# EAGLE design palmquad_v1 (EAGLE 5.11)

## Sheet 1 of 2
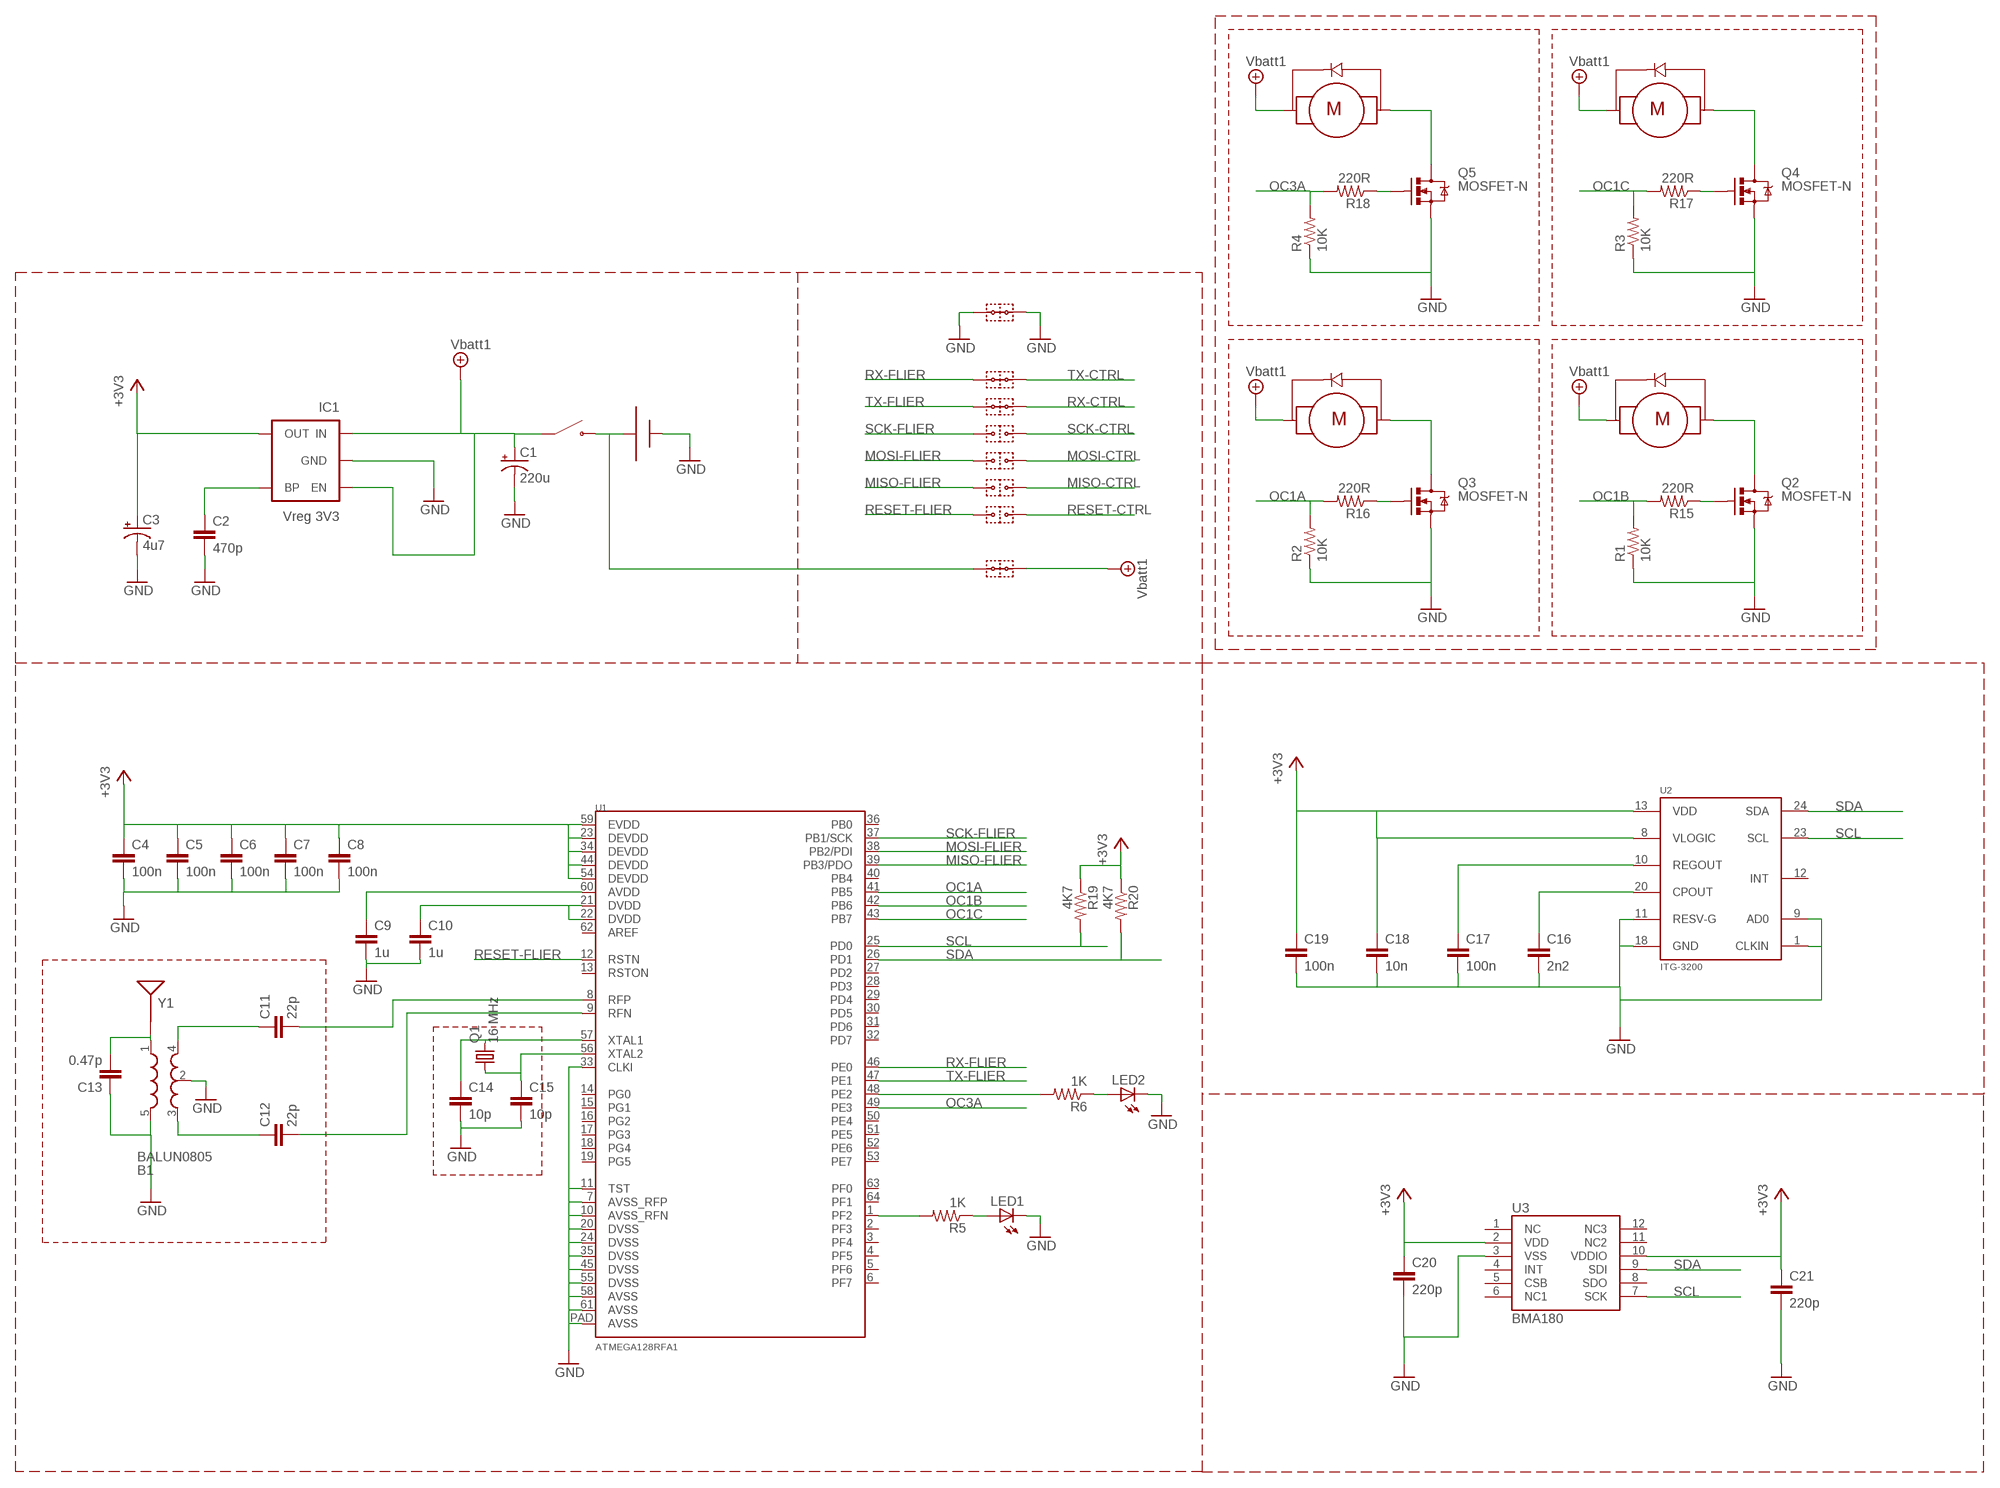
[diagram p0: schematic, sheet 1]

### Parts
B1  BALUN0805  [BALUN]
BATT1  BATT-CONN1  [BATT-CONN-1]
C1  220u  CPOL-USD  [PANASONIC_D]
C2  470p  C-EUC0603  [C0603]
C3  4u7  CPOL-USSMCA  [SMC_A]
C4  100n  C-EUC0603  [C0603]
C5  100n  C-EUC0603  [C0603]
C6  100n  C-EUC0603  [C0603]
C7  100n  C-EUC0603  [C0603]
C8  100n  C-EUC0603  [C0603]
C9  1u  C-EUC0603  [C0603]
C10  1u  C-EUC0603  [C0603]
C11  22p  C-EUC0603  [C0603]
C12  22p  C-EUC0603  [C0603]
C13  0.47p  C-EUC0603  [C0603]
C14  10p  C-EUC0603  [C0603]
C15  10p  C-EUC0603  [C0603]
C16  2n2  C-EUC0603  [C0603]
C17  100n  C-EUC0603  [C0603]
C18  10n  C-EUC0603  [C0603]
C19  100n  C-EUC0603  [C0603]
C20  220p  C-EUC0603  [C0603]
C21  220p  C-EUC0603  [C0603]
IC1  Vreg 3V3  V_REG_LDOSMD  [SOT23-5]
LED1  LEDCHIPLED_0603  [CHIPLED_0603]
LED2  LEDCHIPLED_0603  [CHIPLED_0603]
M1  MOTORARM-CORNER  [MOTOR-CORNER-2]
M2  MOTORARM-CORNER  [MOTOR-CORNER-2]
M3  MOTORARM-CORNER  [MOTOR-CORNER-2]
M4  MOTORARM-CORNER  [MOTOR-CORNER-2]
Q1  16 MHz  CRYSTALCTS406  [CTS406]
Q2  MOSFET-N  MOSFET-NCHANNELSMD  [SOT23-3]
Q3  MOSFET-N  MOSFET-NCHANNELSMD  [SOT23-3]
Q4  MOSFET-N  MOSFET-NCHANNELSMD  [SOT23-3]
Q5  MOSFET-N  MOSFET-NCHANNELSMD  [SOT23-3]
R1  10K  R-US_R0603  [R0603]
R2  10K  R-US_R0603  [R0603]
R3  10K  R-US_R0603  [R0603]
R4  10K  R-US_R0603  [R0603]
R5  1K  R-US_R0603  [R0603]
R6  1K  R-US_R0603  [R0603]
R15  220R  R-US_R0603  [R0603]
R16  220R  R-US_R0603  [R0603]
R17  220R  R-US_R0603  [R0603]
R18  220R  R-US_R0603  [R0603]
R19  4K7  R-US_R0603  [R0603]
R20  4K7  R-US_R0603  [R0603]
S2  SWITCH-PWR-SIMPLE  [SWITCH-PWR]
U1  ATMEGA128RFA1  [QFN-64]
U2  ITG-3200  [QFN-24]
U3  BMA180  [LGA12]
U$1  EDGE-CONN-O-1  [EDGE-CONN-O]
U$2  EDGE-CONN-O-1  [EDGE-CONN-O]
U$3  EDGE-CONN-O-1  [EDGE-CONN-O]
U$4  EDGE-CONN-O-1  [EDGE-CONN-O]
X1  EDGE-CONN-C-1  [EDGE-CONN-C]
X2  EDGE-CONN-C-1  [EDGE-CONN-C]
X5  EDGE-CONN-C-1  [EDGE-CONN-C]
X6  EDGE-CONN-C-1  [EDGE-CONN-C]
Y1  ANTENNA2COMBO1  [ANTENNA-COMBO1]

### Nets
+3V3_FLIER: C3.+ C4.1 C5.1 C6.1 C7.1 C8.1 C18.1 C19.1 C20.1 C21.1 IC1.5(OUT) R19.1 R20.1 U1.23(DEVDD) U1.34(DEVDD) U1.44(DEVDD) U1.54(DEVDD) U1.59(EVDD) U2.8(VLOGIC) U2.13(VDD) U3.2(VDD) U3.10(VDDIO) ; supply symbol labelled +3V3
GND: B1.2(GND) B1.5(GND) BATT1.2 C1.- C2.2 C3.- C4.2 C5.2 C6.2 C7.2 C8.2 C9.2 C10.2 C13.1 C14.2 C15.2 C16.2 C17.2 C18.2 C19.2 C20.2 C21.2 IC1.2(GND) LED1.C LED2.C Q2.2(S) Q3.2(S) Q4.2(S) Q5.2(S) R1.1 R2.1 R3.1 R4.1 U1.7(AVSS_RFP) U1.10(AVSS_RFN) U1.11(TST) U1.20(DVSS) U1.24(DVSS) U1.33(CLKI) U1.35(DVSS) U1.45(DVSS) U1.55(DVSS) U1.58(AVSS) U1.61(AVSS) U1.PAD(AVSS) U2.1(CLKIN) U2.9(AD0) U2.11(RESV-G) U2.18(GND) U3.3(VSS) X6.1 X6.2 ; also sheet 2
MISO-CTRL: U$3.2 ; also sheet 2
MISO-FLIER: U1.39(PB3/PDO) U$3.1
MOSI-CTRL: U$2.2 ; also sheet 2
MOSI-FLIER: U1.38(PB2/PDI) U$2.1
MS1: B1.1(IN) C13.2 Y1.ANT(SIGNAL)
N$1: C2.1 IC1.4(BP)
N$3: C11.2 U1.8(RFP)
N$4: C10.1 U1.21(DVDD) U1.22(DVDD)
N$5: C9.1 U1.60(AVDD)
N$6: B1.3(OUT1) C12.1
N$7: B1.4(OUT2) C11.1
N$8: C12.2 U1.9(RFN)
N$9: C14.1 Q1.3 U1.57(XTAL1)
N$10: C15.1 Q1.1 U1.56(XTAL2)
N$16: C16.1 U2.20(CPOUT)
N$17: C17.1 U2.10(REGOUT)
N$18: M2.B@1 Q3.3(D)
N$19: M3.A@1 Q4.3(D)
N$20: M4.A@1 Q5.3(D)
N$21: M1.B@1 Q2.3(D)
N$23: R5.2 U1.1(PF2)
N$24: LED1.A R5.1
N$40: BATT1.1 S2.P$2 X5.1
N$43: R6.2 U1.48(PE2)
N$44: LED2.A R6.1
N$45: Q5.1(G) R18.1
N$46: Q4.1(G) R17.1
N$47: Q2.1(G) R15.1
N$48: Q3.1(G) R16.1
OC1A: R2.2 R16.2 U1.41(PB5)
OC1B: R1.2 R15.2 U1.42(PB6)
OC1C: R3.2 R17.2 U1.43(PB7)
OC3A: R4.2 R18.2 U1.49(PE3)
RESET-CTRL: U$4.2 ; also sheet 2
RESET-FLIER: U1.12(RSTN) U$4.1
RX-CTRL: X2.2 ; also sheet 2
RX-FLIER: U1.46(PE0) X1.1
SCK-CTRL: U$1.2 ; also sheet 2
SCK-FLIER: U1.37(PB1/SCK) U$1.1
SCL: R19.2 U1.25(PD0) U2.23(SCL) U3.7(SCK)
SDA: R20.2 U1.26(PD1) U2.24(SDA) U3.9(SDI)
TX-CTRL: X1.2 ; also sheet 2
TX-FLIER: U1.47(PE1) X2.1
VBATT-FLIER: C1.+ IC1.1(IN) IC1.3(EN) M1.A@1 M2.A@1 M3.B@1 M4.B@1 S2.P$1 ; supply symbol labelled Vbatt1
VBATT_CHG: X5.2 ; supply symbol labelled Vbatt1 ; also sheet 2
Unconnected: U1.2(PF3) U1.3(PF4) U1.4(PF5) U1.5(PF6) U1.6(PF7) U1.13(RSTON) U1.14(PG0) U1.15(PG1) U1.16(PG2) U1.17(PG3) U1.18(PG4) U1.19(PG5) U1.27(PD2) U1.28(PD3) U1.29(PD4) U1.30(PD5) U1.31(PD6) U1.32(PD7) U1.36(PB0) U1.40(PB4) U1.50(PE4) U1.51(PE5) U1.52(PE6) U1.53(PE7) U1.62(AREF) U1.63(PF0) U1.64(PF1) U2.12(INT) U3.1(NC) U3.4(INT) U3.5(CSB) U3.6(NC1) U3.8(SDO) U3.11(NC2) U3.12(NC3)

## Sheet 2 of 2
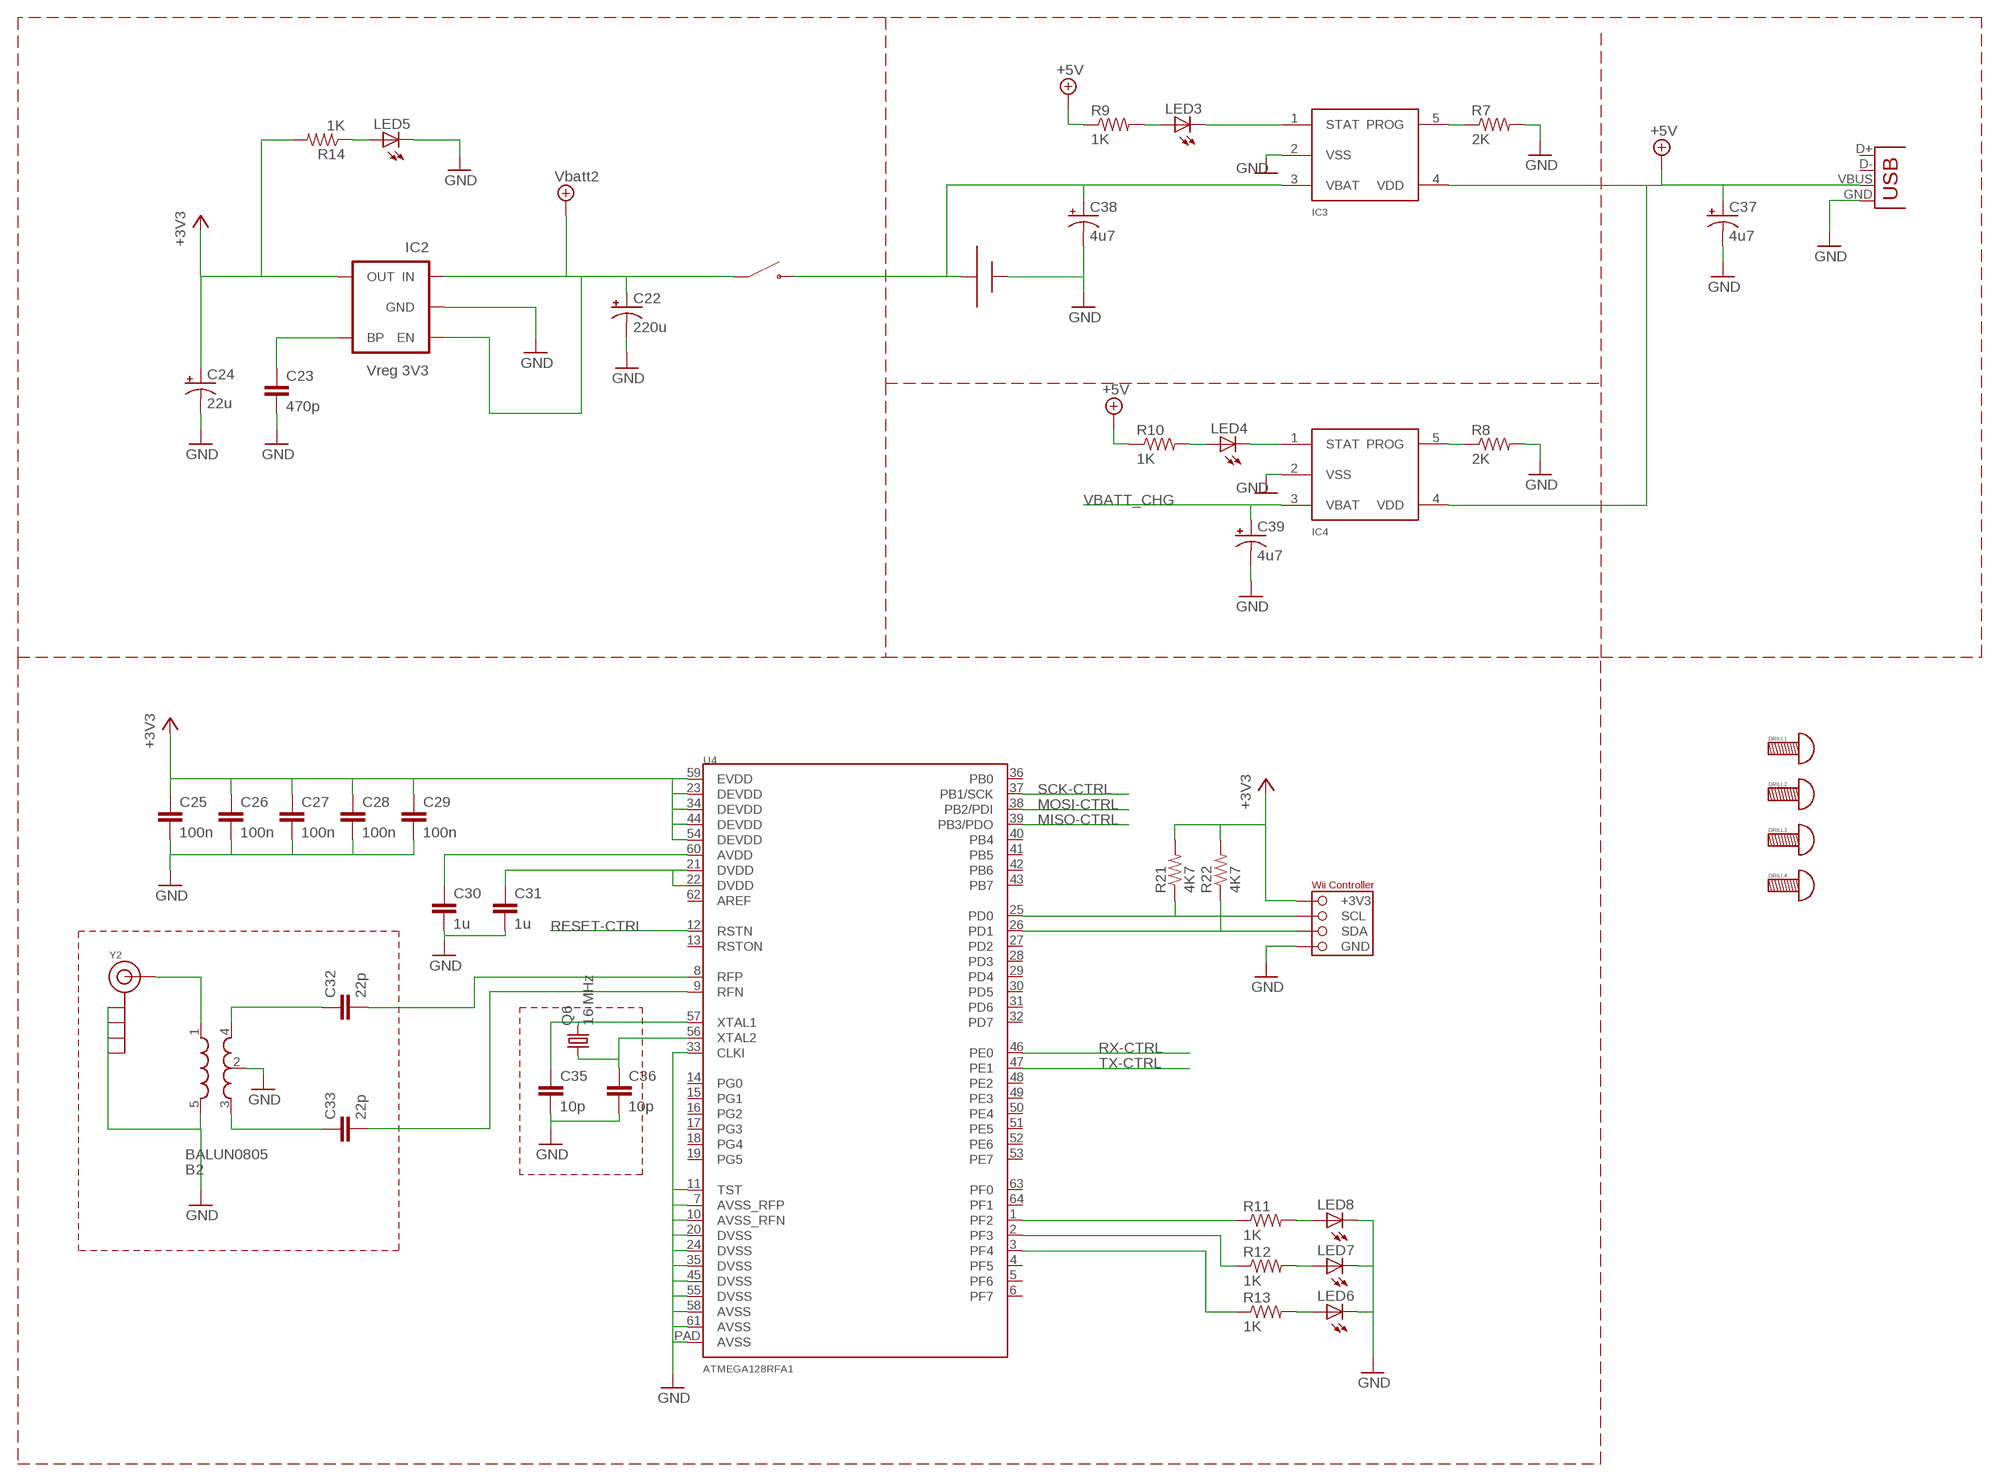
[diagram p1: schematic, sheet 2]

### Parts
B2  BALUN0805  [BALUN]
BATT2  BATT-CONN1  [BATT-CONN-1]
C22  220u  CPOL-USSMCC  [SMC_C]
C23  470p  C-EUC0603  [C0603]
C24  22u  CPOL-USSMCB  [SMC_B]
C25  100n  C-EUC0603  [C0603]
C26  100n  C-EUC0603  [C0603]
C27  100n  C-EUC0603  [C0603]
C28  100n  C-EUC0603  [C0603]
C29  100n  C-EUC0603  [C0603]
C30  1u  C-EUC0603  [C0603]
C31  1u  C-EUC0603  [C0603]
C32  22p  C-EUC0603  [C0603]
C33  22p  C-EUC0603  [C0603]
C35  10p  C-EUC0603  [C0603]
C36  10p  C-EUC0603  [C0603]
C37  4u7  CPOL-USSMCA  [SMC_A]
C38  4u7  CPOL-USSMCA  [SMC_A]
C39  4u7  CPOL-USSMCA  [SMC_A]
DRILL1  HOLE-4-40  [HOLE-4-40]
DRILL2  HOLE-4-40  [HOLE-4-40]
DRILL3  HOLE-4-40  [HOLE-4-40]
DRILL4  HOLE-4-40  [HOLE-4-40]
IC2  Vreg 3V3  V_REG_LDOSMD  [SOT23-5]
IC3  MCP-LI-CHARGER-1  [SOT23-5]
IC4  MCP-LI-CHARGER-1  [SOT23-5]
LED3  LEDCHIPLED_0603  [CHIPLED_0603]
LED4  LEDCHIPLED_0603  [CHIPLED_0603]
LED5  LEDCHIPLED_0603  [CHIPLED_0603]
LED6  LEDCHIPLED_0603  [CHIPLED_0603]
LED7  LEDCHIPLED_0603  [CHIPLED_0603]
LED8  LEDCHIPLED_0603  [CHIPLED_0603]
Q6  16 MHz  CRYSTALCTS406  [CTS406]
R7  2K  R-US_R0603  [R0603]
R8  2K  R-US_R0603  [R0603]
R9  1K  R-US_R0603  [R0603]
R10  1K  R-US_R0603  [R0603]
R11  1K  R-US_R0603  [R0603]
R12  1K  R-US_R0603  [R0603]
R13  1K  R-US_R0603  [R0603]
R14  1K  R-US_R0603  [R0603]
R21  4K7  R-US_R0603  [R0603]
R22  4K7  R-US_R0603  [R0603]
S1  SWITCH-PWR-CNKOS2  [SWITCH-SPDT-CNK-OS2]
U4  ATMEGA128RFA1  [QFN-64]
USB  USBSMD  [USB-MINIB]
X11  WII-CONN  [WII-CONN-2]
Y2  SMA_EDGE  [SMA-EDGE]

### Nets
+3V3_CTRL: C24.+ C25.1 C26.1 C27.1 C28.1 C29.1 IC2.5(OUT) R14.2 R21.2 R22.2 U4.23(DEVDD) U4.34(DEVDD) U4.44(DEVDD) U4.54(DEVDD) U4.59(EVDD) X11.+3V3 ; supply symbol labelled +3V3
GND: B2.2(GND) B2.5(GND) BATT2.2 C22.- C23.2 C24.- C25.2 C26.2 C27.2 C28.2 C29.2 C30.2 C31.2 C35.2 C36.2 C37.- C38.- C39.- IC2.2(GND) IC3.2(VSS) IC4.2(VSS) LED5.C LED6.C LED7.C LED8.C R7.2 R8.2 U4.7(AVSS_RFP) U4.10(AVSS_RFN) U4.11(TST) U4.20(DVSS) U4.24(DVSS) U4.33(CLKI) U4.35(DVSS) U4.45(DVSS) U4.55(DVSS) U4.58(AVSS) U4.61(AVSS) U4.PAD(AVSS) USB.GND X11.GND Y2.GND@0(GND) Y2.GND@1(GND) Y2.GND@2(GND) Y2.GND@3(GND) ; also sheet 1
MISO-CTRL: U4.39(PB3/PDO) ; also sheet 1
MOSI-CTRL: U4.38(PB2/PDI) ; also sheet 1
N$2: LED5.A R14.1
N$11: IC3.5(PROG) R7.1
N$12: LED6.A R13.2
N$13: LED7.A R12.2
N$14: LED8.A R11.2
N$15: IC4.5(PROG) R8.1
N$22: R11.1 U4.1(PF2)
N$25: C23.1 IC2.4(BP)
N$26: C31.1 U4.21(DVDD) U4.22(DVDD)
N$27: C30.1 U4.60(AVDD)
N$28: B2.1(IN) Y2.SIG(SIGNAL)
N$29: B2.3(OUT1) C33.1
N$30: B2.4(OUT2) C32.1
N$31: C32.2 U4.8(RFP)
N$32: C33.2 U4.9(RFN)
N$33: C35.1 Q6.3 U4.57(XTAL1)
N$34: C36.1 Q6.1 U4.56(XTAL2)
N$35: LED3.A R9.2
N$36: IC3.1(STAT) LED3.C
N$37: LED4.A R10.2
N$38: IC4.1(STAT) LED4.C
N$39: BATT2.1 C38.+ IC3.3(VBAT) S1.2
N$41: R12.1 U4.2(PF3)
N$42: R13.1 U4.3(PF4)
RESET-CTRL: U4.12(RSTN) ; also sheet 1
RX-CTRL: U4.46(PE0) ; also sheet 1
SCK-CTRL: U4.37(PB1/SCK) ; also sheet 1
SCL-2: R21.1 U4.25(PD0) X11.SCL
SDA-2: R22.1 U4.26(PD1) X11.SDA
TX-CTRL: U4.47(PE1) ; also sheet 1
VBATT-CTRL: C22.+ IC2.1(IN) IC2.3(EN) S1.1 ; supply symbol labelled Vbatt2
VBATT_CHG: C39.+ IC4.3(VBAT) ; also sheet 1
VUSB: C37.+ IC3.4(VDD) IC4.4(VDD) R9.1 R10.1 USB.VBUS ; supply symbol labelled +5V
Unconnected: U4.4(PF5) U4.5(PF6) U4.6(PF7) U4.13(RSTON) U4.14(PG0) U4.15(PG1) U4.16(PG2) U4.17(PG3) U4.18(PG4) U4.19(PG5) U4.27(PD2) U4.28(PD3) U4.29(PD4) U4.30(PD5) U4.31(PD6) U4.32(PD7) U4.36(PB0) U4.40(PB4) U4.41(PB5) U4.42(PB6) U4.43(PB7) U4.48(PE2) U4.49(PE3) U4.50(PE4) U4.51(PE5) U4.52(PE6) U4.53(PE7) U4.62(AREF) U4.63(PF0) U4.64(PF1) USB.D+ USB.D-

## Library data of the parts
B1 B2 = palmquad_alpha:BALUN
BATT1 BATT2 = palmquad_alpha:BATT-CONN
C1 C3 C22 C24 C37-C39 = rcl:CPOL-US: POLARIZED CAPACITOR, American symbol
C2 C4-C21 C23 C25-C33 C35 C36 = rcl:C-EU: CAPACITOR, European symbol
DRILL1-DRILL4 = palmquad_alpha:HOLE
IC1 IC2 = palmquad_alpha:V_REG_LDO: Voltage Regulator LDO Standard 150mA LDO voltage regulator in SOT-23 layout. Micrel part MIC5205. BP (by-pass) pin is used to lower output noise with 470pF cap.
IC3 IC4 = palmquad_alpha:MCP-LI-CHARGER-1
LED1-LED8 = led:LED: LED
M1-M4 = palmquad_alpha:MOTOR
Q1 Q6 = crystal:CRYSTAL: CRYSTAL
Q2-Q5 = palmquad_alpha:MOSFET-NCHANNEL
R1-R22 = rcl:R-US_: RESISTOR, American symbol
S1 S2 = palmquad_alpha:SWITCH-PWR
U1 U4 = palmquad_alpha:ATMEGA128RFA1
U2 = palmquad_alpha:ITG-3200: ITG-3200 3-axis gyro, digital output, qfn24 package
U3 = palmquad_alpha:BMA180
U$1-U$4 = palmquad_alpha:EDGE-CONN-O
USB = palmquad_alpha:USB: USB Connectors USB-B-PTH is fully proven SKU : PRT-00139 USB-miniB is fully proven SKU : PRT-00587 USB-A-PCB is untested. USB-A-H is throughly reviewed, but untested. Spark Fun Electronics SKU : PRT-00437 USB-B-SMT is throughly reviewed, but untested. Needs silkscreen touching up. USB-A-S has not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
X1 X2 X5 X6 = palmquad_alpha:EDGE-CONN-C
X11 = palmquad_alpha:WII-CONN
Y1 = palmquad_alpha:ANTENNA2: Antenna
Y2 = palmquad_alpha:SMA_EDGE: SMA Antenna Connector End launch SMA connector. The paste layer has been removed so that the connector can be hand soldered onto the board after reflow.

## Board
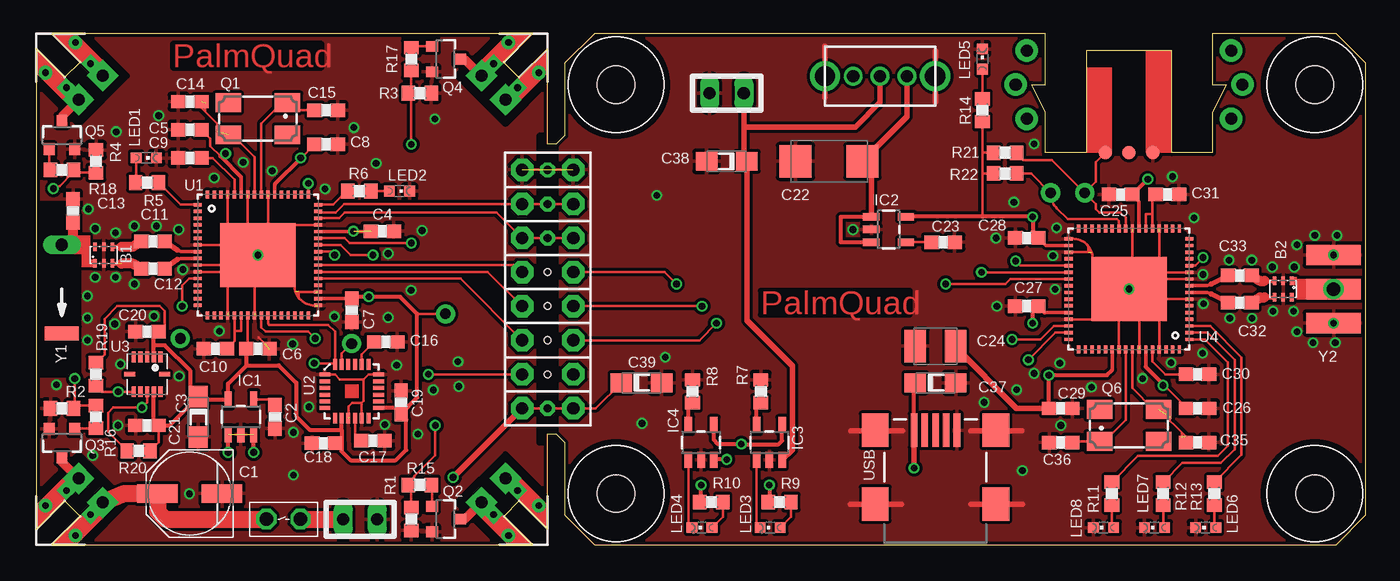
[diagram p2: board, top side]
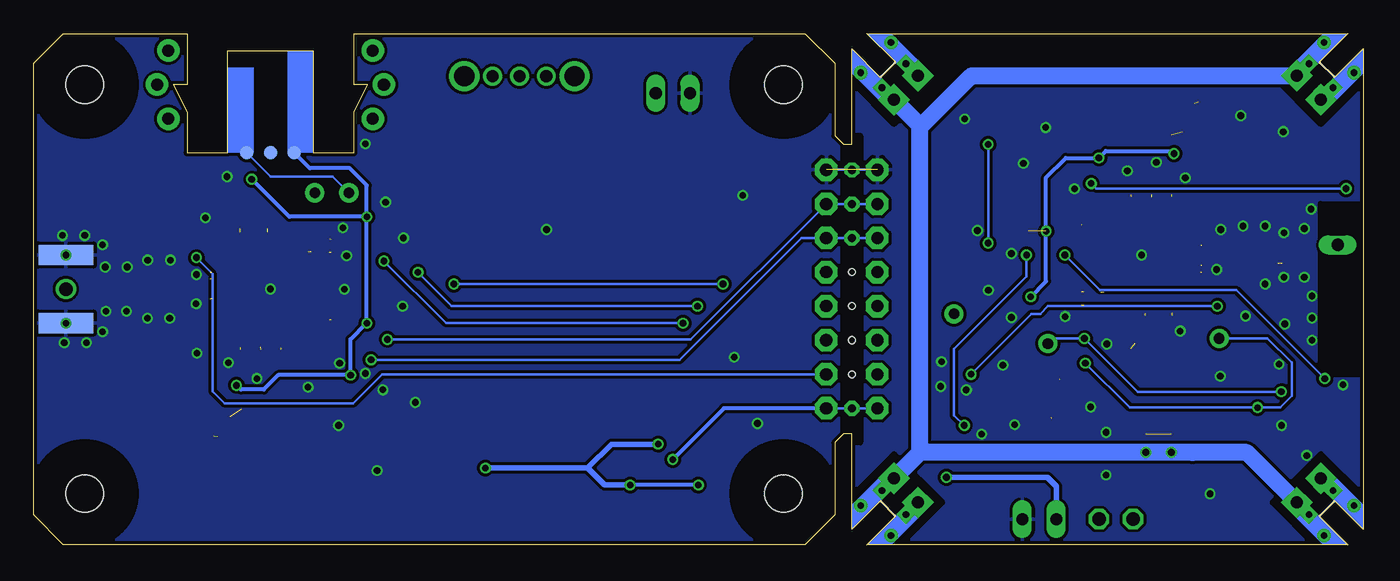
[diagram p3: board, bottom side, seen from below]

Size 99.06 x 38.1 mm. Coordinates in mm from the lower left corner, seen from the top.
Outline: 0,1.14 2.13,3.27 3.27,2.13 1.14,0 36.96,0 34.83,2.13 35.97,3.27 38.1,1.14 38.1,8.26 38.73,8.26 39.37,7.62 39.37,2.22 41.59,0 96.84,0 99.06,2.22 99.06,35.88 96.84,38.1 87.63,38.1 87.63,34.29 88.65,34.29 87.63,32.26 87.63,29.21 84.58,29.21 84.58,36.83 78.23,36.83 78.23,29.21 75.18,29.21 75.18,32.26 74.17,34.29 75.18,34.29 75.18,38.1 41.59,38.1 39.37,35.88 39.37,30.48 38.73,29.84 38.1,29.84 38.1,36.96 36.01,34.86 35.94,34.86 34.86,35.94 34.86,36.01 36.96,38.1 1.14,38.1 3.27,35.97 2.13,34.83 0,36.96 0,1.14
Copper layers (1*16): Top 0.035mm / dielectric 1.5mm / Bottom 0.035mm
Design rules "Fusion_eagle_rule_v1.1_TentedVias3": minimum track width 6mil, minimum drill 0.3mm, track to track 7mil, track to pad 7mil, pad to pad 7mil, via to via 7mil, smd to smd 0mil, copper to edge 10mil, drill to drill 10mil, minimum pad ring 10mil, minimum via ring 6mil, stop-mask expansion 2mil, vias tented up to drill 25mil, thermal gap 10mil
tRestrict: area 0,12.7 to 3.2,25.4; area 37.5,7.6 to 38.7,30.5; area 12.4,17.4 to 20.6,25.7; area 77.3,14.9 to 85.5,23.2; area 7,12 to 9.5,13.4; area 22,10 to 25,12.9; 4 lines
bRestrict: area 0,12.7 to 3.2,25.4; area 37.5,7.6 to 38.7,30.5

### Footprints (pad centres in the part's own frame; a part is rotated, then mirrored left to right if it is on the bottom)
BALUN = smd 0.27 x 0.635: 1 -0.7,-0.616; 2 -0.05,-0.616; 3 0.6,-0.616; 4 0.6,0.616; 5 -0.05,0.616; 6 -0.7,0.616
BATT-CONN-1 = drill 0.9 long: 1 -1.27,0; 2 1.27,0
PANASONIC_D = smd 3 x 1.4: + 2.4,0; - -2.4,0
C0603 = smd 1.1 x 1: 1 -0.85,0; 2 0.85,0
SMC_A = smd 1.6 x 1.4: + -1.5,0; - 1.5,0
SMC_C = smd 2.4 x 2.4: + -2.5,0; - 2.5,0
SMC_B = smd 1.6 x 2.4: + -1.5,0; - 1.5,0
HOLE-4-40 = hole 2.794: 0,0
SOT23-5 = smd 0.55 x 1.2: 1 -0.95,-1.3; 2 0,-1.3; 3 0.95,-1.3; 4 0.95,1.3; 5 -0.95,1.3
CHIPLED_0603 = smd 0.8 x 0.8: A 0,-0.75; C 0,0.75
MOTOR-CORNER-2 = drill 0.9 pad 1.676 square: A@1 -1.27,-5.715; B@1 1.27,-5.715 | drill 0.5 square: A@2 -1.27,-4.445; B@2 1.27,-4.445 | drill 0.5 round: P$1 -1.587,-2.54; P$2 1.587,-2.54
CTS406 = smd 1.9 x 1.4: 1 -2.2,-1.2; 2 2.2,-1.2; 3 2.2,1.2; 4 -2.2,1.2
SOT23-3 = smd 0.8 x 0.9: 1 -0.95,-1; 2 0.95,-1; 3 0,1.1
R0603 = smd 1 x 1.1: 1 -0.85,0; 2 0.85,0
SWITCH-SPDT-CNK-OS2 = drill 0.9 round: 1 0,2.007; 2 0,0; 3 0,-2.007 | drill 1.499 pad 1.905 round: P$4 0,4.102; P$5 0,-4.102
SWITCH-PWR = drill 1 octagon: P$1 -1.27,0; P$2 1.27,0
QFN-64 = smd 0.6 x 0.25: 1 -4.5,3.75; 2 -4.5,3.25; 3 -4.5,2.75; 4 -4.5,2.25; 5 -4.5,1.75; 6 -4.5,1.25; 7 -4.5,0.75; 8 -4.5,0.25; 9 -4.5,-0.25; 10 -4.5,-0.75; 11 -4.5,-1.25; 12 -4.5,-1.75; 13 -4.5,-2.25; 14 -4.5,-2.75; 15 -4.5,-3.25; 16 -4.5,-3.75; 33 4.5,-3.75; 34 4.5,-3.25; 35 4.5,-2.75; 36 4.5,-2.25; 37 4.5,-1.75; 38 4.5,-1.25; 39 4.5,-0.75; 40 4.5,-0.25; 41 4.5,0.25; 42 4.5,0.75; 43 4.5,1.25; 44 4.5,1.75; 45 4.5,2.25; 46 4.5,2.75; 47 4.5,3.25; 48 4.5,3.75 | smd 0.25 x 0.6: 17 -3.75,-4.5; 18 -3.25,-4.5; 19 -2.75,-4.5; 20 -2.25,-4.5; 21 -1.75,-4.5; 22 -1.25,-4.5; 23 -0.75,-4.5; 24 -0.25,-4.5; 25 0.25,-4.5; 26 0.75,-4.5; 27 1.25,-4.5; 28 1.75,-4.5; 29 2.25,-4.5; 30 2.75,-4.5; 31 3.25,-4.5; 32 3.75,-4.5; 49 3.75,4.5; 50 3.25,4.5; 51 2.75,4.5; 52 2.25,4.5; 53 1.75,4.5; 54 1.25,4.5; 55 0.75,4.5; 56 0.25,4.5; 57 -0.25,4.5; 58 -0.75,4.5; 59 -1.25,4.5; 60 -1.75,4.5; 61 -2.25,4.5; 62 -2.75,4.5; 63 -3.25,4.5; 64 -3.75,4.5 | smd 5.639 x 4.75: PAD 0,0
QFN-24 = smd 0.8 x 0.3: 1 -2,1.25; 2 -2,0.75; 3 -2,0.25; 4 -2,-0.25; 5 -2,-0.75; 6 -2,-1.25; 13 2,-1.25; 14 2,-0.75; 15 2,-0.25; 16 2,0.25; 17 2,0.75; 18 2,1.25 | smd 0.3 x 0.8: 7 -1.25,-2; 8 -0.75,-2; 9 -0.25,-2; 10 0.25,-2; 11 0.75,-2; 12 1.25,-2; 19 1.25,2; 20 0.75,2; 21 0.25,2; 22 -0.25,2; 23 -0.75,2; 24 -1.25,2
LGA12 = smd 0.8 x 0.32: 1 -1.3,1; 2 -1.3,0.5; 3 -1.3,0; 4 -1.3,-0.5; 5 -1.3,-1; 7 1.3,-1; 8 1.3,-0.5; 9 1.3,0; 10 1.3,0.5; 11 1.3,1 | smd 0.32 x 0.8: 6 0,-1.3; 12 0,1.3
EDGE-CONN-O = drill 0.9 pad 1.676 octagon: 1 -1.905,0; 2 1.905,0 | hole 0.5: 0,0
USB-MINIB = smd 2.5 x 0.5: D+ 2.5,0; D- 2.5,0.8; GND 2.5,-1.6; ID 2.5,-0.8; VBUS 2.5,1.6 | smd 2.5 x 2: GND@1 -3,-4.5; GND@2 -3,4.5; GND@3 2.5,4.5; GND@4 2.5,-4.5
EDGE-CONN-C = drill 0.9 pad 1.676 octagon: 1 -1.905,0; 2 1.905,0 | drill 0.6 octagon: C 0,0
WII-CONN-2 = smd 1.016 x 1.016 bottom: +3V3 1.778,7.62; DEV_DET 0,7.62; SDA -1.778,7.62 | smd 1.016 x 1.016: GND -1.778,7.62; NC 0,7.62; SCL 1.778,7.62 | drill 0.9 pad 1.676 round: P$4 -7.62,0; P$5 7.62,0; P$6 -7.62,5.08; P$7 7.62,5.08; P$11 -8.445,2.54; P$12 8.445,2.54
ANTENNA-COMBO1 = drill 0.9 long: ANT 3.302,0 | smd 1.016 x 2.54: NC -3.302,0
SMA-EDGE = smd 1.524 x 4.064: GND@0 0,0; GND@1 5.08,0; SIG 2.54,0 | smd 1.524 x 4.064 bottom: GND@2 0,0; GND@3 5.08,0

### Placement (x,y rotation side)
B1  5.08,21.59 0 top
B2  92.84,19.05 180 top
BATT1  24.13,1.91 0 top
BATT2  51.44,33.66 180 top
C1  11.43,3.81 180 top
C2  17.78,9.53 270 top
C3  12.06,9.53 270 top
C4  25.78,23.37 0 top
C5  11.43,30.92 180 top
C6  16.51,14.61 0 top
C7  23.5,17.46 270 top
C8  21.59,29.84 0 top
C9  11.43,28.83 180 top
C10  13.34,14.61 180 top
C11  8.7,22.61 0 top
C12  8.7,20.57 0 top
C13  2.73,24.89 270 top
C14  11.43,33.02 180 top
C15  21.59,32.38 0 top
C16  26.04,15.11 0 top
C17  25.08,7.75 0 top
C18  21.4,7.56 180 top
C19  27.18,10.6 90 top
C20  8.26,15.88 180 top
C21  8.26,8.89 180 top
C22  59.05,28.57 180 top
C23  67.56,22.55 0 top
C24  66.99,14.8 180 top
C25  80.77,26.1 180 top
C26  86.51,10.16 0 top
C27  73.79,17.78 180 top
C28  73.79,22.86 180 top
C29  76.33,10.16 0 top
C30  86.51,12.7 0 top
C31  84.26,26.1 0 top
C32  89.66,18.03 180 top
C33  89.66,20.07 180 top
C35  86.51,7.62 0 top
C36  76.33,7.62 180 top
C37  66.99,12.06 0 top
C38  51.44,28.57 180 top
C39  45.09,12.06 0 top
DRILL1  43.18,3.81 0 top
DRILL2  95.25,3.81 0 top
DRILL3  43.18,34.29 0 top
DRILL4  95.25,34.29 0 top
IC1  15.24,9.53 0 top
IC2  63.5,23.5 270 top
IC3  54.61,7.62 0 top
IC4  49.53,7.62 0 top
LED1  8.19,28.83 270 top
LED2  27.05,26.35 270 top
LED3  54.67,1.27 90 top
LED4  49.59,1.27 90 top
LED5  70.48,36.2 0 top
LED6  87.12,1.27 90 top
LED7  83.31,1.27 90 top
LED8  79.5,1.27 90 top
M1  38.1,0 225 top
M2  0,0 135 top
M3  38.1,38.1 315 top
M4  0,38.1 45 top
Q1  16.51,31.75 180 top
Q2  30.48,1.91 270 top
Q3  1.91,7.62 180 top
Q4  30.48,36.2 270 top
Q5  1.91,30.48 0 top
Q6  81.41,8.89 0 top
R1  27.94,1.91 90 top
R2  1.91,10.16 0 top
R3  28.57,33.66 180 top
R4  4.45,28.57 270 top
R5  8.26,26.99 0 top
R6  24.07,26.35 180 top
R7  53.98,11.43 90 top
R8  48.9,11.43 90 top
R9  55.37,3.17 0 top
R10  50.29,3.17 0 top
R11  80.14,3.81 270 top
R12  83.95,3.81 270 top
R13  87.76,3.81 270 top
R14  70.48,32.38 270 top
R15  28.57,4.45 180 top
R16  4.45,9.53 90 top
R17  27.94,36.2 270 top
R18  1.91,27.94 0 top
R19  4.45,12.7 270 top
R20  7.62,6.99 180 top
R21  72.17,29.21 180 top
R22  72.17,27.67 180 top
S1  62.87,34.92 270 top
S2  18.41,1.91 0 top
U1  16.51,21.59 0 top
U2  23.5,11.43 0 top
U3  8.26,12.7 270 top
U4  81.41,19.05 180 top
U$1  38.1,15.24 0 top
U$2  38.1,17.78 0 top
U$3  38.1,20.32 0 top
U$4  38.1,12.7 0 top
U$5  [ARM-MOCK]  35.56,35.56 45 top
U$6  [ARM-MOCK]  2.54,35.56 135 top
U$7  [ARM-MOCK]  2.54,2.54 225 top
U$8  [ARM-MOCK]  35.56,2.54 315 top
USB  66.99,6.03 90 top
X1  38.1,22.86 0 top
X2  38.1,25.4 0 top
X5  38.1,10.16 0 top
X6  38.1,27.94 180 top
X11  81.41,36.83 180 top
Y1  1.91,19.05 90 top
Y2  96.65,16.51 90 top

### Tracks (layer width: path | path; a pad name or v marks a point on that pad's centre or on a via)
+3V3_CTRL  (via drill 0.5)
  Top 0.203: C29.1 75.45,10.19 | C29.1 75.48,10.23 | C26.1 85.64,10.27 83.89,12.01 83.69,12.01 | C25.1 81.62,25.82 | C29.1 75.44,10.16 | 74.23,17.38 C27.1 | 70.48,24.45 70.48,27.67 | 70.48,29.21 R14.2 | 70.48,29.21 R21.2 | 70.48,27.67 R22.2 | 70.48,27.67 70.48,29.21
  Top 0.254: U4.34 75.2,22.3 C28.1 | 75.12,17.3 U4.44 | 80.16,13.03 U4.54 | 82.66,13.25 U4.59 | U4.23 82.16,25.56 C25.1
  Top 0.305: C27.1 75.12,17.3 | 82.66,13.25 83.89,12.01 83.95,11.96 v83.95,11.87 | 80.16,13.03 79.76,12.64 v75.44,12.64 75.44,10.16 | v74.23,16.51 74.23,17.38 | v82.8,27.24 81.66,26.1 C25.1 | C28.1 74.23,23.27 v74.23,24.45 70.48,24.45 IC2.5
  Top 0.406: C24.+ 68.39,14.8 73.03,10.16 C29.1
  Bottom 0.305: X11.+3V3 78.49,28.07 75.5,28.07 74.23,26.8 v74.23,24.45 | v83.95,11.87 83.63,11.56 81.92,11.56 80.83,12.64 v75.44,12.64 75.44,15.3 v74.23,16.51 v74.23,24.45 | v74.23,24.45 80.01,24.45 v82.8,27.24
+3V3_FLIER  (via drill 0.5, 0.8 pad 1.42)  (1 unrouted)
  Top 0.203: 8.76,16.16 C20.1 9.11,16.22 9.55,16.22 9.55,17.43 9.2,17.78 6.03,17.78 5.08,16.84 5.08,14.19 R19.1 | 8.76,9.24 C21.1 9.11,7.62 R20.1 | C5.1 12.95,30.25 12.95,29.72 13.72,28.96 | 23.5,18.34 C7.1 23.66,18.48 | U1.23 15.76,14.61 C6.1 | 22.75,7.68 C18.1 | 26.75,10.18 C19.1 27.18,9.34 27.56,9.34 | 11.63,10.82 C3.+ 11.49,11.03 | 24.93,23.34 C4.1 | v19.68,28.83 19.72,28.83 C8.1 | 28.38,17.21 v30.48,17.21
  Top 0.254: 17.76,26.86 U1.54 | 15.26,27.41 U1.59 | 23.5,18.34 U1.34 | 8.76,14.86 U3.2 | U1.44 24.93,23.34
  Top 0.279: U3.2 8.76,16.16 | 8.76,9.24 U3.10 | 26.75,10.18 U2.13 | U2.8 22.75,8.57 22.75,7.68
  Top 0.305: 19.72,28.83 17.76,26.86 | 15.26,27.41 13.72,28.96 13.91,29.15 v14.1,29.15 | 22.75,7.68 22.75,6.96 23.42,6.29 26.78,6.29 27.56,7.06 27.56,9.34 | 11.63,10.82 IC1.5 14.29,11.99 15.66,13.36 | 11.49,11.03 11.49,12.94 9.57,14.86 8.76,14.86 | C21.1 9.93,8.89 C3.+ | 15.66,13.36 C6.1 | 15.66,13.36 18.07,13.36 19.37,12.06 19.37,9.58 20.37,8.57 22.75,8.57 | 23.66,18.48 v24.77,18.48 27.11,18.48 28.38,17.21 28.38,10.96 C19.1
  Bottom 0.203: v23.62,23.37 23.59,23.34 | v24.77,18.48 24.83,18.48
  Bottom 0.305: v14.1,29.15 14.29,29.34 19.18,29.34 v19.68,28.83 22.16,28.83 23.62,27.37 v23.62,23.37 23.62,19.62 v24.77,18.48
GND  (via drill 0.5)  (28 unrouted)
  Top 0.203: 17.02,14.99 16.57,15.43 | 14.26,17.27 14.26,19.46 | 16.26,17.23 16.26,19.41 | 18.77,23.84 20.96,23.84 | 17.27,23.77 17.27,25.95 | 15.76,23.72 15.76,25.91 | 14.26,23.75 14.26,25.93 | 12.09,20.84 14.27,20.84 | 12.14,20.34 14.33,20.34 | 12.11,22.34 14.3,22.34 | 20.8,17.83 20.73,17.83 arc-90 19.23,19.33 | 83.62,20.29 85.8,20.29 | 83.61,19.8 85.8,19.8 | 83.58,18.3 85.76,18.3 | 83.66,14.72 83.66,16.9 | 82.16,14.73 82.16,16.92 | 80.66,14.67 80.66,16.86 | 77,16.8 79.19,16.8 | 81.66,21.13 81.66,23.32 | 83.66,21.11 83.66,23.29 | 19.33,18.84 20.82,18.84 | 77.02,22.8 77.23,22.8 arc-90 78.69,21.34 | 78.61,21.8 77.06,21.8 | 24.24,10.57 24.24,9.58 | 24.24,10.57 24.38,10.71 24.38,12.32 | 24.38,12.32 22.62,12.32 | 23.25,9.5 23.25,10.3 23.52,10.57 24.24,10.57 | 25.3,12.69 24.75,12.69 24.38,12.32 | 21.69,12.68 22.25,12.68 22.61,12.32 | 19.56,18.4 19.56,18.83 | 78.37,21.82 78.37,22.24
  Top 0.406: 60.71,8.47 64.52,8.47 | 69.62,8.5 73.43,8.5 | 69.65,3.02 73.46,3.02 | 60.64,3.01 64.45,3.01 | 58.75,33.34 58.75,37.15 | 66.97,32.99 66.97,36.8
  other vias: 96.65,21.59 96.65,16.51 93.66,17.4 93.92,15.88 92.08,20.7 93.92,22.35 92.14,17.4 90.55,21.21 95.25,23.05 96.9,23.05 95.12,15.05 96.77,15.05 5.91,23.24 3.87,25.02 5.91,19.94 4.38,19.94 4.38,23.56 10.91,20.51 86.93,20.14 86.95,17.95 45.13,9.04 15.41,28.49 17.57,27.86 13.25,27.35 9.12,31.98 25.97,8.95 7.3,23.75 7.3,19.43 5.95,30.78 29.7,31.73 23.66,31.1 28.43,8.24 26.84,13.38 20.3,10.27 19.16,8.36 10.65,12.55 1.5,11.92 11.41,3.79 22.2,17 13.63,15.92 84.65,27.43 76.01,23.62 71.5,22.86 71.56,17.78 82.42,12.38 76.33,8.89 76.26,13.53 26.2,16.94 27.92,18.97 31.41,13.63 31.48,11.79 29.57,11.54 8.77,17.04 5.85,16.45 88.92,16.87 90.57,16.87 88.86,21.21 60.83,23.5 19.09,14.97 86.89,14.27 28.74,23.41 26.2,21.7 21.51,26.52 46.86,13.97 46.23,26.04 93.73,20.7 3.81,18.54 3.81,16.89 84.54,13.57 75.9,19.03 86.25,24.37 75.74,21.54 19.16,5.19 4.21,6.65 74.35,12.76 70.61,10.6 78.61,11.75 72.83,25.53 25.32,28.43 16.51,21.59 81.41,19.05 8.95,23.75 10.6,23.5 6.27,13.46 73.47,5.52 6.09,8.89 3.81,15.24 74.33,29.87 73.04,11.54
  pour Top (isolate 0.216): -0.32,38.42 38.1,38.42 38.1,29.21 39.37,30.48 39.37,38.42 99.38,38.42 99.38,-0.32 39.37,-0.32 39.37,7.62 38.1,8.89 38.1,-0.32 -0.32,-0.32
  pour Bottom (isolate 0.216): -0.32,38.42 38.1,38.42 38.1,29.21 39.37,30.48 39.37,38.42 99.38,38.42 99.38,-0.32 39.37,-0.32 39.37,7.62 38.1,8.89 38.1,-0.32 -0.32,-0.32
MISO-CTRL  (via drill 0.5)
  Top 0.203: U4.39 72.57,19.8 72.2,19.43 v67.75,19.43 | v47.69,19.43 46.8,20.32 U$3.2
  Bottom 0.203: v47.69,19.43 v67.75,19.43
MISO-FLIER
  Top 0.203: U1.39 35.67,20.84 U$3.1
MOSI-CTRL  (via drill 0.5)
  Top 0.203: v70.42,20.3 U4.38 | U$2.2 v49.59,17.78
  Bottom 0.203: v49.59,17.78 67.9,17.78 v70.42,20.3
MOSI-FLIER
  Top 0.203: U1.38 33.63,20.34 U$2.1
MS1
  Top 0.203: 2.73,22.35 2.98,22.35 3.68,21.65 3.68,20.97 B1.1
  Top 0.762: C13.2 2.73,22.35 Y1.ANT
N$1
  Top 0.203: IC1.4 17.33,10.82 C2.1
N$2
  Top 0.203: LED5.A R14.1
N$3
  Top 0.254: U1.8 10.75,21.84 10.5,21.97
  Top 0.406: C11.2 10.5,21.97
N$4
  Top 0.203: C10.1 14.76,15.18 14.76,15.94 | 14.76,15.94 U1.21 | U1.22 15.26,15.94 14.76,15.94
N$5
  Top 0.203: C9.1 13.16,28.83 14.76,27.23 U1.60
N$6  (1 unrouted)
  Top 0.305: B1.3 6.01,20.97
  Top 0.762: 6.35,20.95 7.21,20.95 C12.1
N$7
  Top 0.305: B1.4 6.33,22.21
  Top 0.762: 6.33,22.21 7.2,22.21 C11.1
N$8
  Top 0.254: 10.5,21.24 10.75,21.34 U1.9
  Top 0.406: C12.2 10.5,21.24
N$9  (2 unrouted)
  Top 0.203: U1.57 16.26,28.89 14.6,30.55 Q1.3 12.28,32.58 C14.1 | 13.46,31.39 13.46,30.78 | 12.57,32.91 12.57,32.31
N$10
  Top 0.203: U1.56 16.76,31.39 18.32,32.95 Q1.1 arc90 19.27,32.38 C15.1
N$11
  Top 0.305: IC3.5 53.66,10.58 R7.1
N$12
  Top 0.203: R13.2 87.76,1.39 LED6.A
N$13
  Top 0.203: R12.2 83.95,1.39 LED7.A
N$14
  Top 0.203: R11.2 80.14,1.39 LED8.A
N$15
  Top 0.305: IC4.5 48.58,10.58 R8.1
N$16
  Top 0.203: U2.20 24.25,14.17 C16.1
N$17
  Top 0.203: U2.10 23.75,7.68 C17.1
N$18
  Top 0.635: Q3.3 1.91,6.18 M2.B@1
N$19
  Top 0.635: Q4.3 31.92,36.2 M3.A@1
N$20
  Top 0.635: Q5.3 1.91,31.92 M4.A@1
N$21
  Top 0.635: Q2.3 31.92,1.91 M1.B@1
N$22
  Top 0.203: U4.1 87.06,15.3 88.77,13.59 88.77,7.37 88.01,6.6 82.08,6.6 R11.1
N$23
  Top 0.203: U1.1 10.75,25.34 R5.2
N$24
  Top 0.203: LED1.A 7.44,27.02 R5.1
N$25
  Top 0.203: IC2.4 C23.1
N$26
  Top 0.203: U4.21 83.16,24.64 | 83.16,24.64 83.16,25.72 C31.1 | U4.22 82.66,24.64 83.16,24.64
N$27
  Top 0.203: U4.60 83.16,13.66 84.12,12.7 C30.1
N$28  (via drill 1)
  Top 0.203: 96.15,19.55 Y2.SIG 96.03,19.67 B2.1
  other vias: 96.65,19.05
N$29
  Top 0.305: 91.52,19.67 B2.3
  Top 0.762: 91.52,19.67 91.17,19.67 C33.1
N$30
  Top 0.305: 91.52,18.43 B2.4
  Top 0.762: 91.52,18.43 91.17,18.43 C32.1
N$31
  Top 0.254: U4.8 87.24,18.8 87.53,18.68
  Top 0.406: 87.53,18.68 C32.2
N$32
  Top 0.254: U4.9 87.24,19.3 87.53,19.42
  Top 0.406: 87.53,19.42 C33.2
N$33  (2 unrouted)
  Top 0.203: U4.57 81.66,11.67 83.24,10.09 Q6.3 85.64,8.06 C35.1 | 84.45,9.27 84.45,9.53 | 85.34,8.03 85.34,8.33
N$34
  Top 0.203: U4.56 81.16,9.29 79.56,7.69 Q6.1 77.25,7.69 C36.1
N$35
  Top 0.203: LED3.A 56.22,2.07 R9.2
N$36
  Top 0.203: IC3.1 53.66,1.27 LED3.C
N$37
  Top 0.203: LED4.A 51.14,2.07 R10.2
N$38
  Top 0.203: IC4.1 48.58,1.6 LED4.C
N$39
  Top 0.406: IC3.3 56.33,7.08 56.33,13.34 52.94,16.73 C38.+ 52.7,28.8 BATT2.1 52.7,31.11 61.01,31.11 62.87,32.97 S1.2
N$40  (via drill 0.5)
  Top 0.406: v31.05,5.02 X5.1
  Top 1.27: S2.P$2 BATT1.1
  Bottom 0.406: BATT1.1 22.86,4.35 23.53,5.02 v31.05,5.02
N$41
  Top 0.203: U4.2 87.26,15.8 89.28,13.78 89.28,7.11 88.27,6.1 85.38,6.1 R12.1
N$42
  Top 0.203: U4.3 87.46,16.3 89.79,13.97 89.79,6.69 R13.1
N$43
  Top 0.203: U1.48 22.13,25.34 22.76,25.97 22.84,25.97 R6.2
N$44
  Top 0.203: R6.1 LED2.A
N$45
  Top 0.203: R18.1 0.95,28.04 Q5.1
N$46
  Top 0.203: R17.1 28.04,37.15 Q4.1
N$47
  Top 0.203: R15.1 arc-90 29.48,4.39 Q2.1
N$48
  Top 0.203: Q3.1 2.91,8.68 R16.1
OC1A  (via drill 0.5)
  Top 0.203: U1.41 21.98,21.84 v22.23,21.59 | v2.86,12.38 2.86,10.26 R2.2 2.97,10.38 R16.2
  Bottom 0.203: v2.86,12.38 9.46,18.99 19.62,18.99 v22.23,21.59
OC1B  (via drill 0.5)
  Top 0.203: U1.42 22.68,22.34 23.43,21.59 v25.08,21.59 | v29.72,8.89 29.72,6.67 28.17,5.12 28,4.72 R15.2 27.94,4.23 R1.2
  Bottom 0.203: v25.08,21.59 25.08,20 30.48,14.61 30.48,9.65 v29.72,8.89
OC1C  (via drill 0.5)
  Top 0.203: U1.43 22.99,22.84 23.35,22.48 v27.94,22.48 | v27.94,29.84 27.94,33.66 | 27.94,33.66 R17.2 | 27.94,33.66 R3.2
  Bottom 0.203: v27.94,22.48 v27.94,29.84
OC3A  (via drill 0.5)
  Top 0.203: v20.26,26.92 U1.49 | v1.27,26.54 1.73,26.73 2.75,27.76 R18.2 2.75,27.73 R4.2
  Bottom 0.203: v1.27,26.54 19.88,26.54 v20.26,26.92
RESET-CTRL  (via drill 0.5)
  Top 0.203: U4.12 86.33,20.8 v86.93,21.4
  Bottom 0.203: U$4.2 73.09,12.7 75.25,10.54 84.84,10.54 85.72,11.43 85.72,20.19 v86.93,21.4
RESET-FLIER  (via drill 0.5)
  Top 0.203: U1.12 11.38,19.84 10.86,19.31 v10.86,17.78 | v29.21,12.7 U$4.1
  Bottom 0.203: v10.86,17.78 23.5,17.78 24.07,17.21 24.7,17.21 v29.21,12.7
RX-CTRL  (via drill 0.5)
  Top 0.203: U4.46 75.8,16.3 74.8,15.3 v72.71,15.3
  Bottom 0.203: v72.71,15.3 50.1,15.3 X2.2
RX-FLIER
  Top 0.203: U1.46 22.56,24.34 22.99,24.77 34.29,24.77 X1.1
SCK-CTRL  (via drill 0.5)
  Top 0.203: v50.67,16.51 49.4,15.24 U$1.2 | U4.37 73.31,20.8 v72.96,21.14
  Bottom 0.203: v50.67,16.51 68.33,16.51 v72.96,21.14
SCK-FLIER
  Top 0.203: U1.37 31.59,19.84 U$1.1
SCL  (via drill 0.5, 0.8 pad 1.42)
  Top 0.203: U1.25 16.76,16.2 17.09,15.88 20.26,15.88 v20.77,15.37 | U2.23 22.75,14.24 v23.5,14.99 | U3.7 v6.1,11.4 4.89,11.4 R19.2
  Bottom 0.203: v6.1,11.4 16.8,11.4 v20.77,15.37 23.11,15.37 v23.5,14.99
SCL-2  (via drill 0.8 pad 1.42)
  Top 0.203: U4.25 81.16,24.38 80.77,24.77 79.18,24.77 78.93,25.02 78.93,25.4 v78.11,26.23 | X11.SCL 78.93,28.51 78.93,27.05 v78.11,26.23 | R21.1 73.02,29.16 73.52,28.66 75.67,28.66 v78.11,26.23
SDA  (via drill 0.5, 0.8 pad 1.42)
  Top 0.203: U1.26 17.26,16.48 17.36,16.38 21.75,16.38 22.25,15.89 U2.24 22.15,13.53 v20.7,13.53 | U3.9 8.26,10.6 v7.87,10.22 5.74,10.22 5.35,9.83 5.35,8.41 R20.2
  Bottom 0.203: v20.7,13.53 17.4,10.22 v7.87,10.22 6.19,10.22 5.33,11.07 5.33,13.57 7.13,15.37 v10.73,15.37
SDA-2  (via drill 0.8 pad 1.42)
  Top 0.203: U4.26 80.66,24.11 80.51,24.26 76.85,24.26 76.05,25.06 arc-45 v75.56,26.23 74.12,27.67 R22.1
  Bottom 0.203: X11.SDA 81.41,27.43 76.77,27.43 v75.56,26.23
TX-CTRL  (via drill 0.5)
  Top 0.203: U4.47 75.93,15.8 v73.92,13.78
  Bottom 0.203: v73.92,13.78 50.93,13.78 41.85,22.86 X1.2
TX-FLIER
  Top 0.203: U1.47 21.09,24.77 22.29,24.77 22.92,25.4 X2.1
VBATT-CTRL
  Top 0.305: IC2.1 59.94,24.45 59.94,22.55 IC2.3
  Top 0.406: S1.1 64.87,31.89 C22.+ 62.2,27.93 IC2.1
VBATT-FLIER  (via drill 0.5)  (1 unrouted)
  Top 0.305: v14.29,6.87 IC1.1 | v16.19,6.87 IC1.3
  Top 1.27: M2.A@1 6.55,3.81 C1.+ 9.03,2.46 9.59,1.91 S2.P$1
  Bottom 0.203: v14.29,6.87 12.71,6.86 12.7,6.87
  Bottom 1.27: 33.02,6.87 M1.A@1 | 33.02,6.87 33.02,31.11 | 33.02,31.11 33.02,31.23 M3.B@1 | M4.B@1 29.18,34.96 33.02,31.11 | 33.02,6.87 12.7,6.87 8.67,6.87 M2.A@1
VBATT_CHG  (via drill 0.5)
  Top 0.203: X5.2 41.68,10.16 C39.+
  Top 0.305: IC4.3 50.48,6.35 v51.44,6.35
  Bottom 0.305: v51.44,6.35 47.62,10.16 X5.2
VUSB  (via drill 0.5)
  Top 0.305: IC3.4 55.56,7.75 55.3,7.49 v52.53,7.49 50.8,7.49 50.48,7.81 IC4.4 | v54.61,4.45 54.61,3.26 R9.1 54.61,3.17 | R10.1 49.53,3.26 | 49.53,3.26 v49.53,4.45 | 49.53,3.26 49.53,3.17 | C37.+ 65.39,11.96 USB.VBUS
  Top 0.406: v65.39,5.71 USB.VBUS
  Bottom 0.305: v49.53,4.45 v54.61,4.45
  Bottom 0.406: 57.78,5.71 v65.39,5.71 | 57.78,5.71 56.52,4.45 v54.61,4.45 | 57.78,5.71 56.01,7.49 v52.53,7.49
(copper drawn outside any net)
  shapes: Top area x5

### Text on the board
Top: PalmQuad | PalmQuad
tStop: PalmQuad | PalmQuad
_tsilk: OFF | ON | BAT | +V | GND | GND | GND | Wiimote Extension | SER> | SER< | <SER | MISO | MISO | MOSI | MOSI | SCK | SCK | RST | RST | Vbatt | Vbatt | +V | BAT | GND | SW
